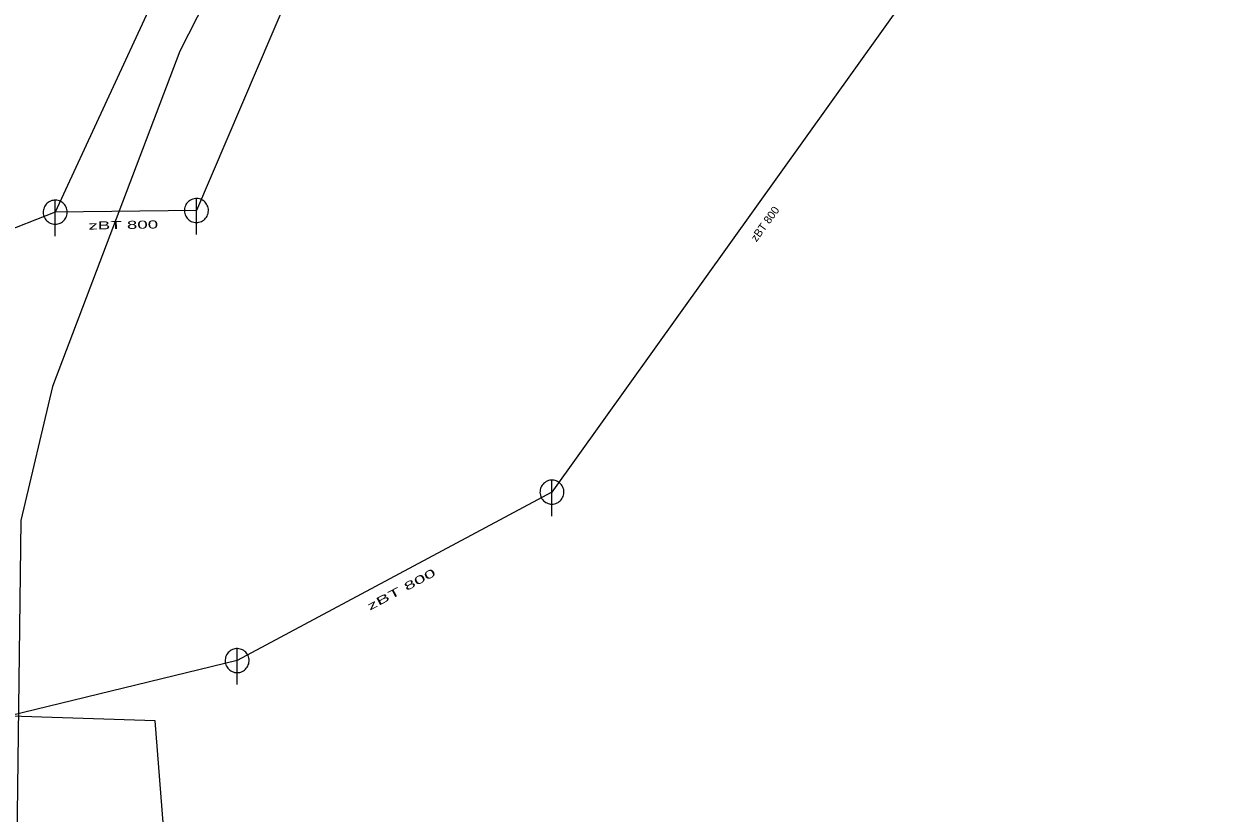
# Model space of a CAD drawing. Extents: x -688432 to -687974, y -973332 to -972704.
# Drawn here: x -688148.9 to -688049.6, y -972903.2 to -972837.5 of the extents above; entities that cross this region are included whole.
import ezdxf
from ezdxf.enums import TextEntityAlignment as Align

# ---------------------------------------------------------------- set-up
doc = ezdxf.new("R2010")
doc.units = 0
doc.header["$LTSCALE"] = 0.27
for name, color, linetype, lineweight in [('1', 7, 'Continuous', 25), ('14', 7, 'Continuous', 25), ('17', 7, 'Continuous', 25), ('22', 7, 'Continuous', 13)]:
    doc.layers.add(name, color=color, linetype=linetype, lineweight=lineweight)

msp = doc.modelspace()

# ---------------------------------------------------------------- linework, layer by layer
at = {"layer": '1'}
msp.add_lwpolyline([(-688157.895, -972985.064), (-688131.748, -972983.489), (-688134.952, -972934.372), (-688122, -972934.52), (-688122.986, -972921.456), (-688135.938, -972921.308), (-688137.958, -972895.554), (-688157.714, -972894.909), (-688157.93, -972929.126), (-688173.215, -972938.189), (-688162.29, -972954.057)], close=True, dxfattribs=at)
at = {"layer": '14'}
for p, q in [((-688070.998, -972704.286), (-688134.53, -972853.039)), ((-688130.152, -972818.317), (-688146.301, -972853.175)), ((-688069.507, -972827.044), (-688104.9, -972876.493)), ((-688146.3, -972853.175), (-688153.616, -972856.054)), ((-688134.531, -972853.039), (-688146.301, -972853.175)), ((-688104.899, -972876.493), (-688131.138, -972890.529)), ((-688131.138, -972890.529), (-688175.649, -972901.305))]:
    msp.add_line(p, q, dxfattribs=at)
at = {"layer": '17'}
msp.add_lwpolyline([(-688123.609, -972815.609), (-688135.91, -972839.761), (-688146.524, -972867.704), (-688149.164, -972878.87), (-688150.368, -972974.473), (-688134.778, -973051.136), (-688125.903, -973068.701), (-688203.651, -973132.27), (-688148.612, -973199.748), (-688078.631, -973291.807), (-688049.631, -973331.642)], dxfattribs=at)
at = {"layer": '22'}
for p, q in [((-688146.301, -972855.175), (-688146.3, -972852.175)), ((-688134.531, -972855.039), (-688134.53, -972852.039)), ((-688104.9, -972878.493), (-688104.899, -972875.493)), ((-688131.138, -972892.529), (-688131.137, -972889.529))]:
    msp.add_line(p, q, dxfattribs=at)
for points in [[(-688145.301, -972853.175), (-688145.306, -972853.066), (-688145.324, -972852.958), (-688145.354, -972852.852), (-688145.394, -972852.751), (-688145.446, -972852.654), (-688145.508, -972852.564), (-688145.58, -972852.481), (-688145.66, -972852.407), (-688145.748, -972852.341), (-688145.842, -972852.286), (-688145.942, -972852.241), (-688146.047, -972852.208), (-688146.154, -972852.186), (-688146.263, -972852.176), (-688146.373, -972852.178), (-688146.481, -972852.192), (-688146.588, -972852.217), (-688146.691, -972852.254), (-688146.789, -972852.303), (-688146.881, -972852.361), (-688146.967, -972852.43), (-688147.044, -972852.507), (-688147.113, -972852.593), (-688147.172, -972852.685), (-688147.22, -972852.783), (-688147.257, -972852.886), (-688147.283, -972852.993), (-688147.297, -972853.101), (-688147.3, -972853.211), (-688147.29, -972853.32), (-688147.269, -972853.427), (-688147.235, -972853.531), (-688147.191, -972853.631), (-688147.136, -972853.726), (-688147.07, -972853.814), (-688146.996, -972853.894), (-688146.913, -972853.966), (-688146.823, -972854.028), (-688146.727, -972854.08), (-688146.625, -972854.121), (-688146.52, -972854.151), (-688146.412, -972854.169), (-688146.302, -972854.175), (-688146.193, -972854.169), (-688146.085, -972854.151), (-688145.98, -972854.122), (-688145.878, -972854.081), (-688145.781, -972854.029), (-688145.691, -972853.967), (-688145.608, -972853.896), (-688145.533, -972853.816), (-688145.468, -972853.728), (-688145.412, -972853.634), (-688145.368, -972853.534), (-688145.334, -972853.43), (-688145.312, -972853.322), (-688145.302, -972853.213)], [(-688133.531, -972853.039), (-688133.536, -972852.93), (-688133.554, -972852.822), (-688133.584, -972852.716), (-688133.624, -972852.615), (-688133.676, -972852.518), (-688133.738, -972852.428), (-688133.81, -972852.345), (-688133.89, -972852.271), (-688133.978, -972852.205), (-688134.072, -972852.15), (-688134.172, -972852.105), (-688134.277, -972852.072), (-688134.384, -972852.05), (-688134.493, -972852.04), (-688134.603, -972852.042), (-688134.711, -972852.056), (-688134.818, -972852.081), (-688134.921, -972852.118), (-688135.019, -972852.167), (-688135.111, -972852.225), (-688135.197, -972852.294), (-688135.274, -972852.371), (-688135.343, -972852.457), (-688135.402, -972852.549), (-688135.45, -972852.647), (-688135.487, -972852.75), (-688135.513, -972852.857), (-688135.527, -972852.965), (-688135.53, -972853.075), (-688135.52, -972853.184), (-688135.499, -972853.291), (-688135.465, -972853.395), (-688135.421, -972853.495), (-688135.366, -972853.59), (-688135.3, -972853.678), (-688135.226, -972853.758), (-688135.143, -972853.83), (-688135.053, -972853.892), (-688134.957, -972853.944), (-688134.855, -972853.985), (-688134.75, -972854.015), (-688134.642, -972854.033), (-688134.532, -972854.039), (-688134.423, -972854.033), (-688134.315, -972854.015), (-688134.21, -972853.986), (-688134.108, -972853.945), (-688134.011, -972853.893), (-688133.921, -972853.831), (-688133.838, -972853.76), (-688133.763, -972853.68), (-688133.698, -972853.592), (-688133.642, -972853.498), (-688133.598, -972853.398), (-688133.564, -972853.294), (-688133.542, -972853.186), (-688133.532, -972853.077)], [(-688103.9, -972876.493), (-688103.905, -972876.384), (-688103.923, -972876.276), (-688103.953, -972876.17), (-688103.993, -972876.069), (-688104.045, -972875.972), (-688104.107, -972875.882), (-688104.179, -972875.799), (-688104.259, -972875.725), (-688104.347, -972875.659), (-688104.441, -972875.604), (-688104.541, -972875.559), (-688104.646, -972875.526), (-688104.753, -972875.504), (-688104.862, -972875.494), (-688104.972, -972875.496), (-688105.08, -972875.51), (-688105.187, -972875.535), (-688105.29, -972875.572), (-688105.388, -972875.621), (-688105.48, -972875.679), (-688105.566, -972875.748), (-688105.643, -972875.825), (-688105.712, -972875.911), (-688105.771, -972876.003), (-688105.819, -972876.101), (-688105.856, -972876.204), (-688105.882, -972876.311), (-688105.896, -972876.419), (-688105.899, -972876.529), (-688105.889, -972876.638), (-688105.868, -972876.745), (-688105.834, -972876.849), (-688105.79, -972876.949), (-688105.735, -972877.044), (-688105.669, -972877.132), (-688105.595, -972877.212), (-688105.512, -972877.284), (-688105.422, -972877.346), (-688105.326, -972877.398), (-688105.224, -972877.439), (-688105.119, -972877.469), (-688105.011, -972877.487), (-688104.901, -972877.493), (-688104.792, -972877.487), (-688104.684, -972877.469), (-688104.579, -972877.44), (-688104.477, -972877.399), (-688104.38, -972877.347), (-688104.29, -972877.285), (-688104.207, -972877.214), (-688104.132, -972877.134), (-688104.067, -972877.046), (-688104.011, -972876.952), (-688103.967, -972876.852), (-688103.933, -972876.748), (-688103.911, -972876.64), (-688103.901, -972876.531)], [(-688130.138, -972890.529), (-688130.143, -972890.42), (-688130.161, -972890.312), (-688130.191, -972890.206), (-688130.231, -972890.105), (-688130.283, -972890.008), (-688130.345, -972889.918), (-688130.417, -972889.835), (-688130.497, -972889.761), (-688130.585, -972889.695), (-688130.679, -972889.64), (-688130.779, -972889.595), (-688130.884, -972889.562), (-688130.991, -972889.54), (-688131.1, -972889.53), (-688131.21, -972889.532), (-688131.318, -972889.546), (-688131.425, -972889.571), (-688131.528, -972889.608), (-688131.626, -972889.657), (-688131.718, -972889.715), (-688131.804, -972889.784), (-688131.881, -972889.861), (-688131.95, -972889.947), (-688132.009, -972890.039), (-688132.057, -972890.137), (-688132.094, -972890.24), (-688132.12, -972890.347), (-688132.134, -972890.455), (-688132.137, -972890.565), (-688132.127, -972890.674), (-688132.106, -972890.781), (-688132.072, -972890.885), (-688132.028, -972890.985), (-688131.973, -972891.08), (-688131.907, -972891.168), (-688131.833, -972891.248), (-688131.75, -972891.32), (-688131.66, -972891.382), (-688131.564, -972891.434), (-688131.462, -972891.475), (-688131.357, -972891.505), (-688131.249, -972891.523), (-688131.139, -972891.529), (-688131.03, -972891.523), (-688130.922, -972891.505), (-688130.817, -972891.476), (-688130.715, -972891.435), (-688130.618, -972891.383), (-688130.528, -972891.321), (-688130.445, -972891.25), (-688130.37, -972891.17), (-688130.305, -972891.082), (-688130.249, -972890.988), (-688130.205, -972890.888), (-688130.171, -972890.784), (-688130.149, -972890.676), (-688130.139, -972890.567)]]:
    msp.add_lwpolyline(points, close=True, dxfattribs=at)

# ---------------------------------------------------------------- texts
at = {"layer": '1'}
msp.add_text('zBT 800 ', height=0.6667, rotation=54, dxfattribs=at).set_placement((-688086.8084, -972854.2471), align=Align.CENTER)
msp.add_text('zBT 800 ', height=0.6667, rotation=54, dxfattribs=at).set_placement((-688086.8084, -972854.2471), align=Align.CENTER)
msp.add_text('zBT 800 ', height=0.6667, rotation=54, dxfattribs=at).set_placement((-688086.8084, -972854.2471), align=Align.CENTER)
msp.add_text('zBT 800 ', height=0.6667, rotation=54, dxfattribs=at).set_placement((-688086.8084, -972854.2471), align=Align.CENTER)
msp.add_text('zBT 800 ', height=0.6667, rotation=54, dxfattribs=at).set_placement((-688086.8084, -972854.2471), align=Align.CENTER)
for rotation, width, p in [(1, 1.75, (-688140.4028, -972854.5723)), (1, 1.75, (-688140.4028, -972854.5723)), (1, 1.75, (-688140.4028, -972854.5723)), (1, 1.75, (-688140.4028, -972854.5723)), (1, 1.75, (-688140.4028, -972854.5723)), (28, 1.9, (-688117.0955, -972884.7793)), (28, 1.9, (-688117.0955, -972884.7793)), (28, 1.9, (-688117.0955, -972884.7793)), (28, 1.9, (-688117.0955, -972884.7793)), (28, 1.9, (-688117.0955, -972884.7793))]:
    msp.add_text('zBT 800 ', height=0.6667, rotation=rotation, dxfattribs=dict(at, width=width)).set_placement(p, align=Align.CENTER)

doc.saveas('drawing.dxf')
